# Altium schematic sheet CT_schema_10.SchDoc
size 388 x 278 mm
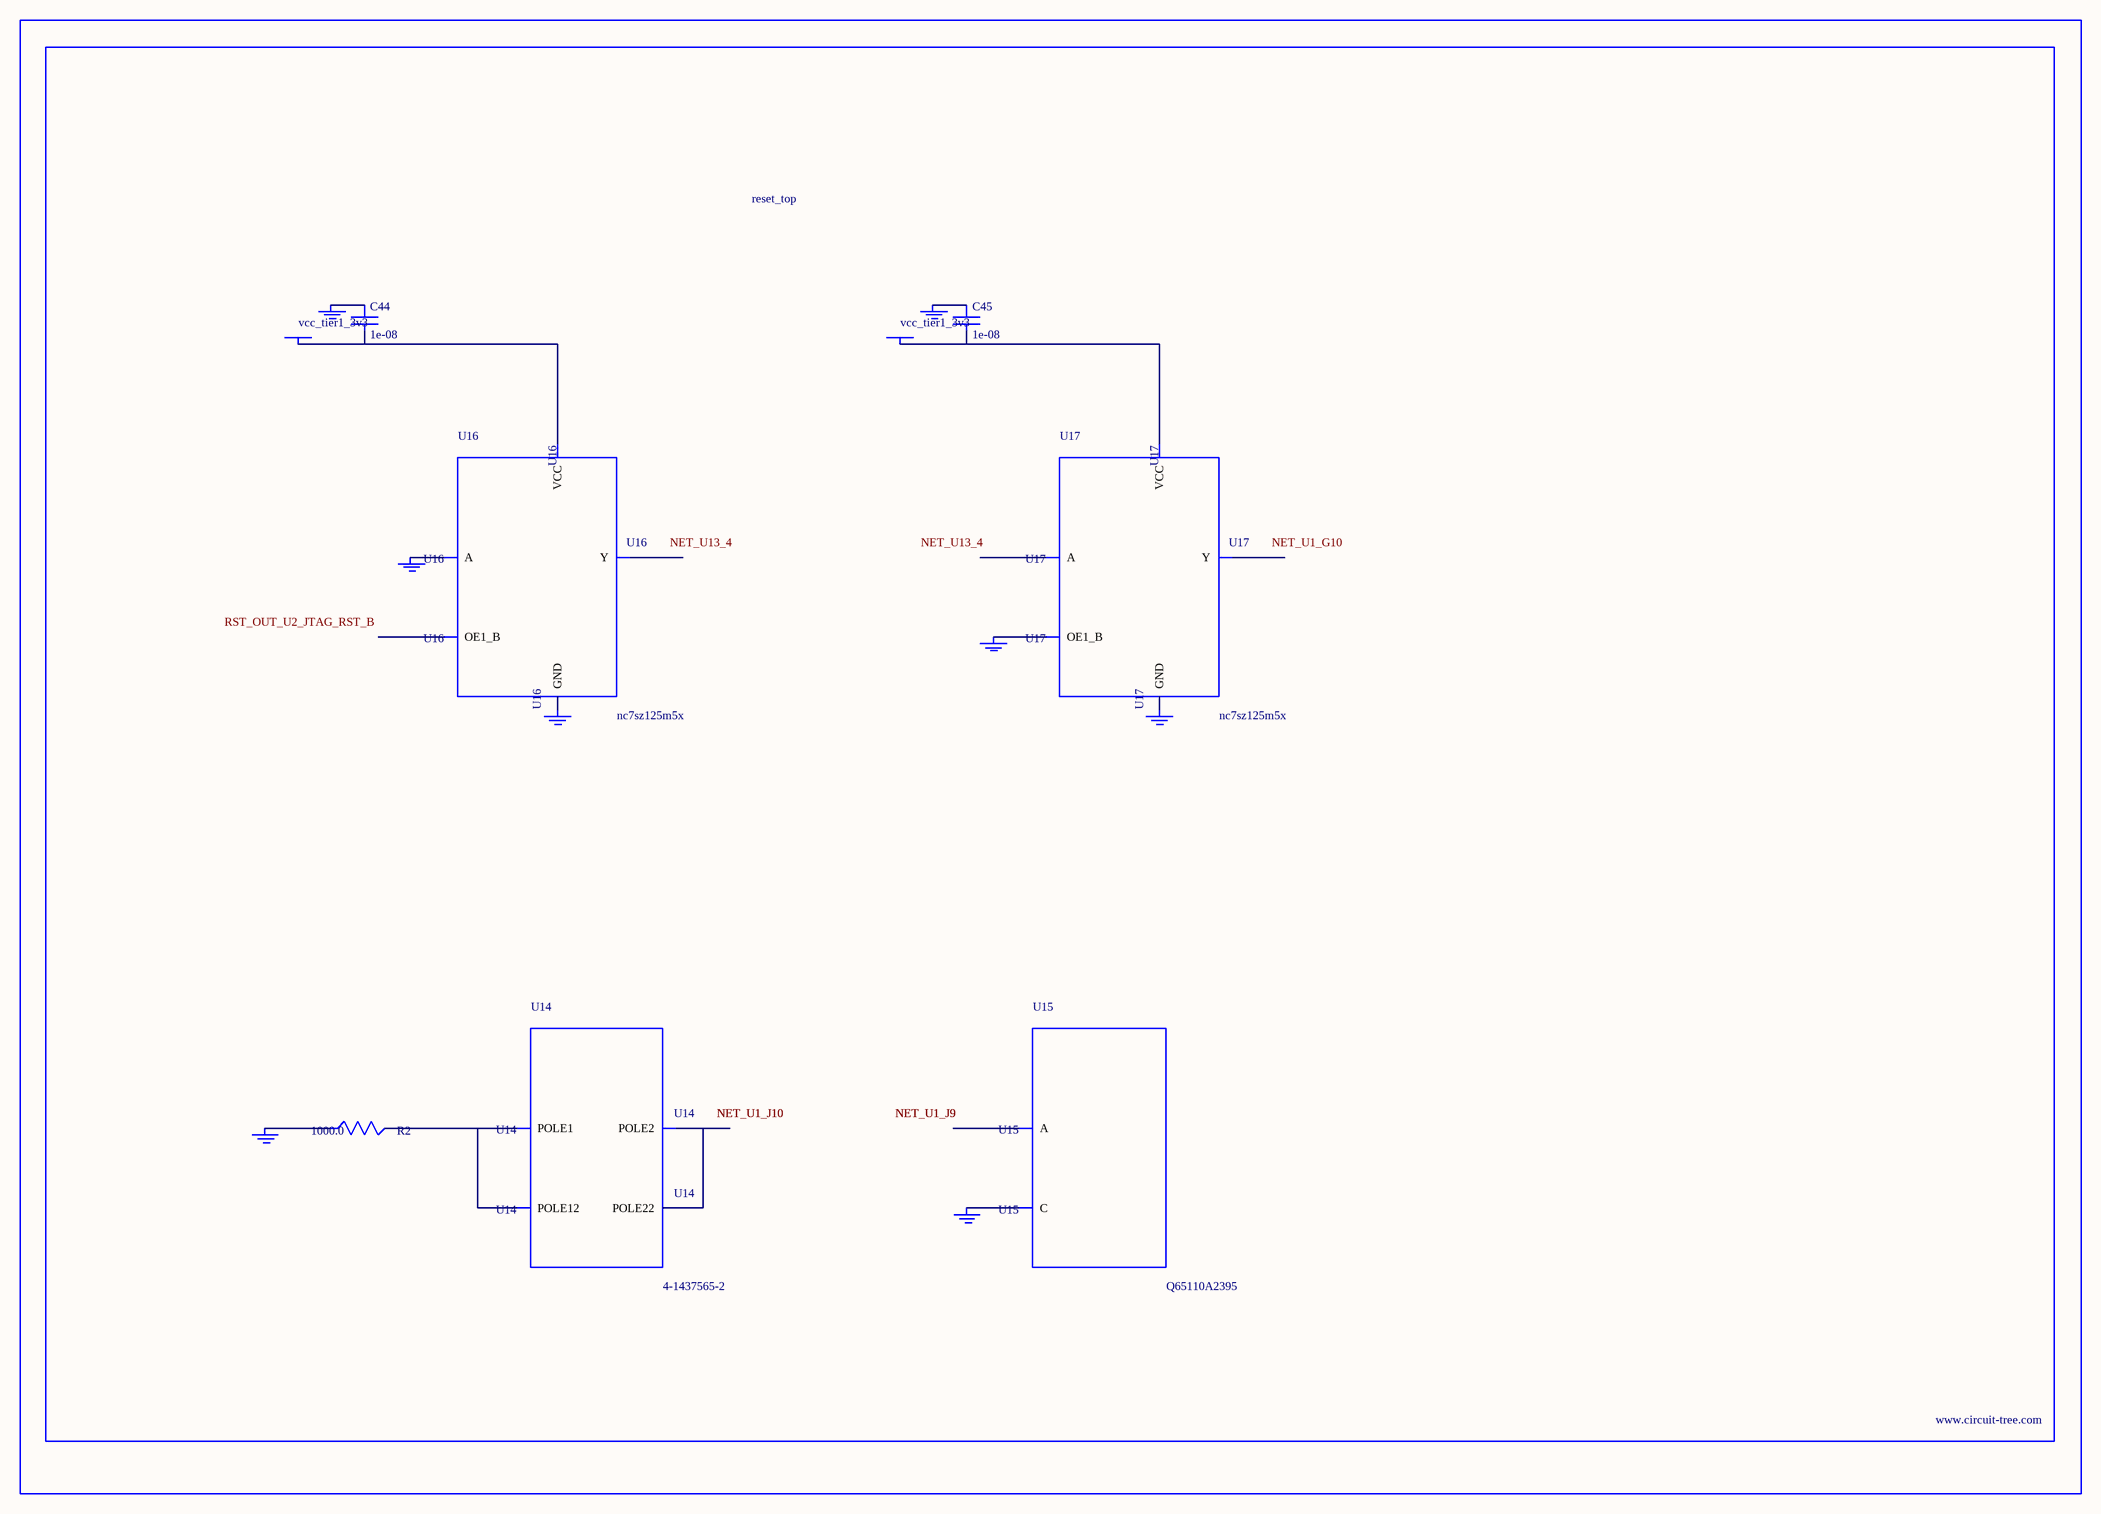
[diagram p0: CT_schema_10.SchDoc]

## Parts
BORDER9  (no value)
C44  1e-08  [C0402]
C45  1e-08  [C0402]
GND_INSTANCE_9_0  (no value)
GND_INSTANCE_9_1  (no value)
GND_INSTANCE_9_2  (no value)
GND_INSTANCE_9_3  (no value)
GND_INSTANCE_9_4  (no value)
GND_INSTANCE_9_5  (no value)
GND_INSTANCE_9_6  (no value)
GND_INSTANCE_9_7  (no value)
POWER_INSTANCE_9_0  vcc_tier1_3v3
POWER_INSTANCE_9_1  vcc_tier1_3v3
R2  1000.0  [R0603]
U14  4-1437565-2  [SW_4-1437565-2]
U15  Q65110A2395  [LGM67K-G1J2-24-Z]
U16  nc7sz125m5x  [NC7SZ125M5X]
U17  nc7sz125m5x  [NC7SZ125M5X]

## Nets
NetC44_1: C44.1 GND_INSTANCE_9_2.0(GND)
NetC44_2: C44.2 POWER_INSTANCE_9_0.0(PWR) U16.5(VCC)
NetC45_1: C45.1 GND_INSTANCE_9_5.0(GND)
NetC45_2: C45.2 POWER_INSTANCE_9_1.0(PWR) U17.5(VCC)
NetGND_INSTANCE_9_0_0: GND_INSTANCE_9_0.0(GND) R2.1
NetGND_INSTANCE_9_1_0: GND_INSTANCE_9_1.0(GND) U15.C
NetGND_INSTANCE_9_3_0: GND_INSTANCE_9_3.0(GND) U16.2(A)
NetGND_INSTANCE_9_4_0: GND_INSTANCE_9_4.0(GND) U16.3(GND)
NetGND_INSTANCE_9_6_0: GND_INSTANCE_9_6.0(GND) U17.1(OE1_B)
NetGND_INSTANCE_9_7_0: GND_INSTANCE_9_7.0(GND) U17.3(GND)
NetR2_2: R2.2 U14.1(POLE1) U14.2(POLE12)
NetU14_3: U14.3(POLE2) U14.4(POLE22)

Not connected (* = marked no-connect by the designer): U15 A; U16 1(OE1_B) 4(Y); U17 2(A) 4(Y)

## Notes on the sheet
- Labels drawn without touching a wire or pin: NET_U1_G10, NET_U13_4, RST_OUT_U2_JTAG_RST_B

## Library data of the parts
BORDER9 = BORDER_PAGE9
C44 C45 = C0402C103K3RAC
GND_INSTANCE_9_0-GND_INSTANCE_9_7 = GND
POWER_INSTANCE_9_0 POWER_INSTANCE_9_1 = PWR
R2 = RC0603JR-071KL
